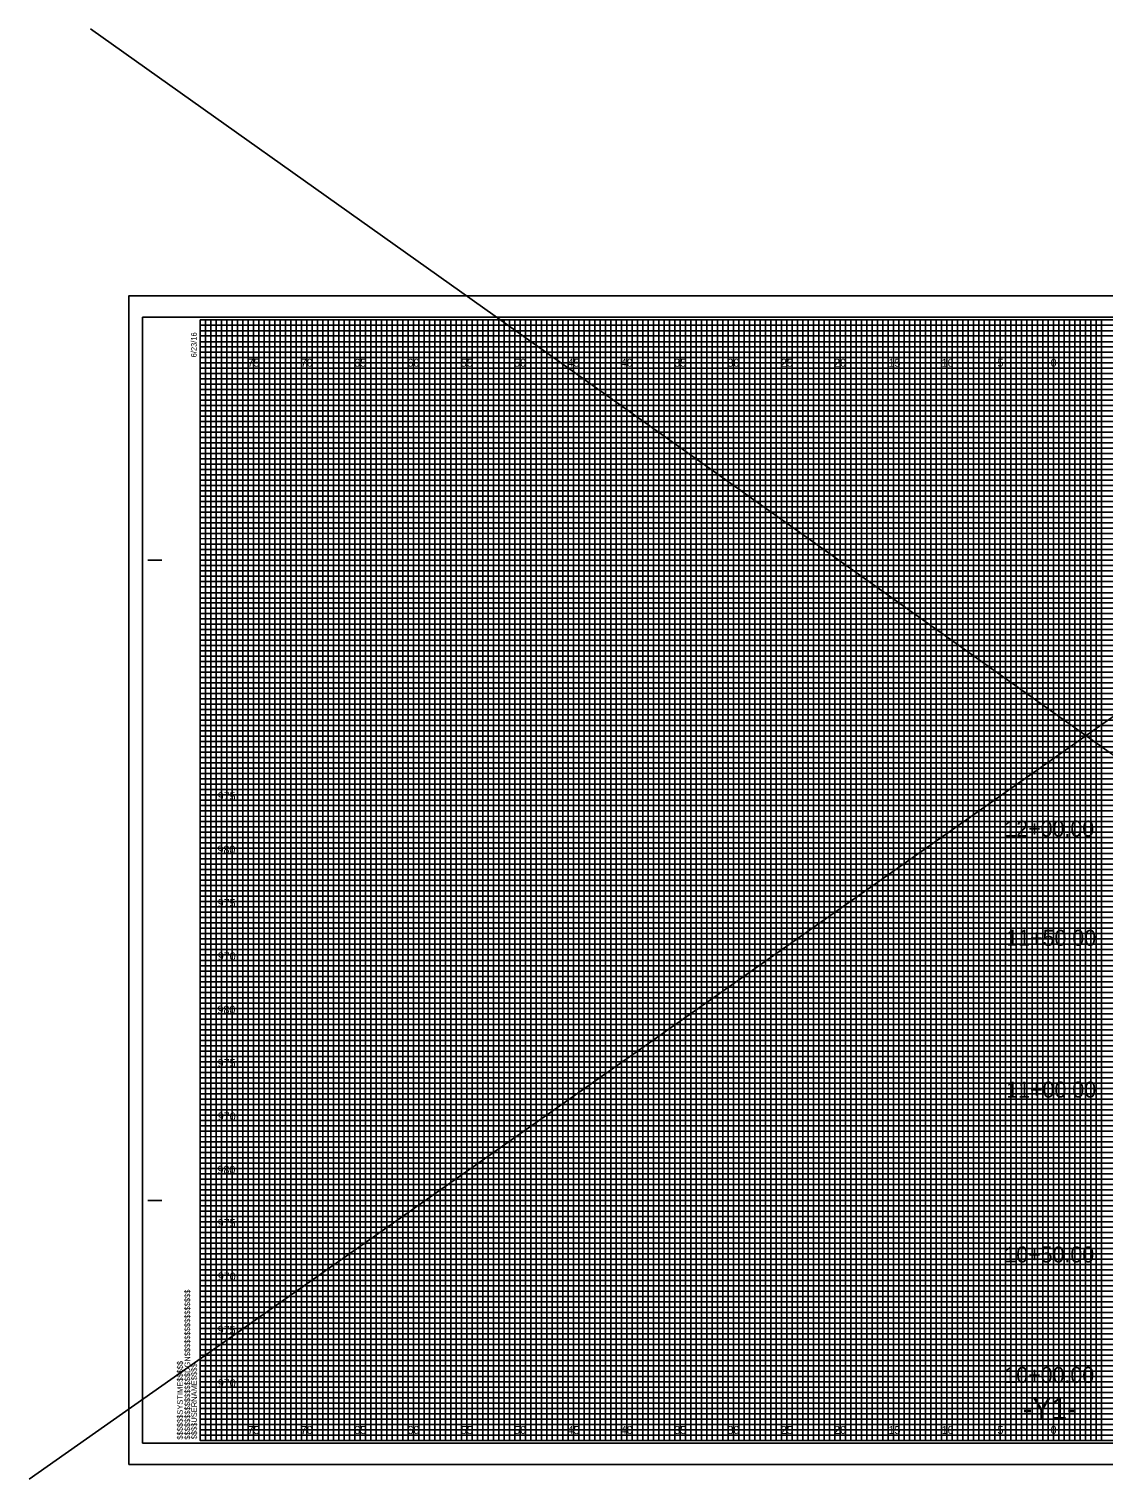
# Model space of a CAD drawing. Extents: x -16 to 178, y -4 to 132.
# Drawn here: x -16.1 to 84.6, y -3.6 to 132.3 of the extents above; entities that cross this region are included whole.
import ezdxf

# ---------------------------------------------------------------- set-up
doc = ezdxf.new("R2010")
doc.units = 0
for name, color, linetype in [('Default', 7, 'Continuous'), ('Exist Cross Section Cell', 7, 'Continuous'), ('Exist XS Center Line Elevation Label', 7, 'Continuous'), ('Exist XS Ground Line', 7, 'Continuous'), ('Prop XS Ditch Standard Text', 7, 'Continuous'), ('Prop XS Dump Level', 7, 'Continuous'), ('Prop XS Finish Grade', 7, 'Continuous'), ('Prop XS Finish Grade Earthwork', 7, 'Continuous'), ('Prop XS Pvmt Edge Slope', 7, 'Continuous'), ('Prop XS SE Text', 7, 'Continuous'), ('Prop XS Side Slope Text', 7, 'Continuous'), ('Prop XS SS Elevation Text', 7, 'Continuous'), ('Prop XS Subgrade CurbGutter', 7, 'Continuous'), ('Prop XS Subgrade Earthwork', 7, 'Continuous')]:
    doc.layers.add(name, color=color, linetype=linetype)

msp = doc.modelspace()

# ---------------------------------------------------------------- linework, layer by layer
at = {"layer": 'Default'}
for p, q in [((178, -1.35), (-10.3, 132.27)), ((-16.05, -3.6), (159.75, 120))]:
    msp.add_line(p, q, dxfattribs=at)
at = {"layer": 'Exist XS Center Line Elevation Label'}
for points in [[(0, 105), (2.5, 105), (2.5, 0), (7.5, 0), (7.5, 105), (12.5, 105), (12.5, 0), (17.5, 0), (17.5, 105), (22.5, 105), (22.5, 0), (27.5, 0), (27.5, 105), (32.5, 105), (32.5, 0), (37.5, 0), (37.5, 105), (42.5, 105), (42.5, 0), (47.5, 0), (47.5, 105), (52.5, 105), (52.5, 0), (57.5, 0), (57.5, 105), (62.5, 105), (62.5, 0), (67.5, 0), (67.5, 105), (72.5, 105), (72.5, 0), (77.5, 0), (77.5, 105), (82.5, 105), (82.5, 0), (87.5, 0)], [(0, 102.5), (137.5, 102.5)], [(0, 92.5), (160, 92.5), (160, 97.5), (0, 97.5)], [(0, 82.5), (160, 82.5), (160, 87.5), (0, 87.5)], [(0, 72.5), (160, 72.5), (160, 77.5), (0, 77.5)], [(0, 62.5), (160, 62.5), (160, 67.5), (0, 67.5)], [(0, 52.5), (160, 52.5), (160, 57.5), (0, 57.5)], [(0, 42.5), (160, 42.5), (160, 47.5), (0, 47.5)], [(0, 32.5), (160, 32.5), (160, 37.5), (0, 37.5)], [(0, 22.5), (160, 22.5), (160, 27.5), (0, 27.5)], [(0, 12.5), (160, 12.5), (160, 17.5), (0, 17.5)], [(0, 2.5), (160, 2.5), (160, 7.5), (0, 7.5)]]:
    msp.add_lwpolyline(points, dxfattribs=at)
at = {"layer": 'Exist XS Ground Line'}
for p, q in [((5, 105), (0, 105)), ((5, 0), (5, 105)), ((15, 105), (10, 105)), ((10, 105), (10, 0)), ((15, 0), (15, 105)), ((25, 105), (20, 105)), ((20, 105), (20, 0)), ((25, 0), (25, 105)), ((35, 105), (30, 105)), ((30, 105), (30, 0)), ((35, 0), (35, 105)), ((45, 105), (40, 105)), ((40, 105), (40, 0)), ((45, 0), (45, 105)), ((55, 105), (50, 105)), ((50, 105), (50, 0)), ((55, 0), (55, 105)), ((65, 105), (60, 105)), ((60, 105), (60, 0)), ((65, 0), (65, 105)), ((75, 105), (70, 105)), ((70, 105), (70, 0)), ((75, 0), (75, 105)), ((85, 105), (80, 105)), ((80, 105), (80, 0)), ((10, 0), (5, 0)), ((20, 0), (15, 0)), ((30, 0), (25, 0)), ((40, 0), (35, 0)), ((50, 0), (45, 0)), ((60, 0), (55, 0)), ((70, 0), (65, 0)), ((80, 0), (75, 0))]:
    msp.add_line(p, q, dxfattribs=at)
for points in [[(0, 100), (160, 100), (160, 95), (0, 95)], [(0, 90), (160, 90), (160, 85), (0, 85)], [(0, 80), (160, 80), (160, 75), (0, 75)], [(0, 70), (160, 70), (160, 65), (0, 65)], [(0, 60), (160, 60), (160, 55), (0, 55)], [(0, 50), (160, 50), (160, 45), (0, 45)], [(0, 40), (160, 40), (160, 35), (0, 35)], [(0, 30), (160, 30), (160, 25), (0, 25)], [(0, 20), (160, 20), (160, 15), (0, 15)], [(0, 10), (160, 10), (160, 5), (0, 5)]]:
    msp.add_lwpolyline(points, dxfattribs=at)
at = {"layer": 'Prop XS Ditch Standard Text'}
for points in [[(0, 0), (0.5, 0), (0.5, 105), (1, 105), (1, 0)], [(1, 0), (1.5, 0), (1.5, 105), (2, 105), (2, 0)], [(2.5, 0), (3, 0), (3, 105), (3.5, 105), (3.5, 0)], [(3.5, 0), (4, 0), (4, 105), (4.5, 105), (4.5, 0)], [(5, 0), (5.5, 0), (5.5, 105), (6, 105), (6, 0)], [(6, 0), (6.5, 0), (6.5, 105), (7, 105), (7, 0)], [(7.5, 0), (8, 0), (8, 105), (8.5, 105), (8.5, 0)], [(8.5, 0), (9, 0), (9, 105), (9.5, 105), (9.5, 0)], [(10, 0), (10.5, 0), (10.5, 105), (11, 105), (11, 0)], [(11, 0), (11.5, 0), (11.5, 105), (12, 105), (12, 0)], [(12.5, 0), (13, 0), (13, 105), (13.5, 105), (13.5, 0)], [(13.5, 0), (14, 0), (14, 105), (14.5, 105), (14.5, 0)], [(15, 0), (15.5, 0), (15.5, 105), (16, 105), (16, 0)], [(16, 0), (16.5, 0), (16.5, 105), (17, 105), (17, 0)], [(17.5, 0), (18, 0), (18, 105), (18.5, 105), (18.5, 0)], [(18.5, 0), (19, 0), (19, 105), (19.5, 105), (19.5, 0)], [(20, 0), (20.5, 0), (20.5, 105), (21, 105), (21, 0)], [(21, 0), (21.5, 0), (21.5, 105), (22, 105), (22, 0)], [(22.5, 0), (23, 0), (23, 105), (23.5, 105), (23.5, 0)], [(23.5, 0), (24, 0), (24, 105), (24.5, 105), (24.5, 0)], [(25, 0), (25.5, 0), (25.5, 105), (26, 105), (26, 0)], [(26, 0), (26.5, 0), (26.5, 105), (27, 105), (27, 0)], [(27.5, 0), (28, 0), (28, 105), (28.5, 105), (28.5, 0)], [(28.5, 0), (29, 0), (29, 105), (29.5, 105), (29.5, 0)], [(30, 0), (30.5, 0), (30.5, 105), (31, 105), (31, 0)], [(31, 0), (31.5, 0), (31.5, 105), (32, 105), (32, 0)], [(32.5, 0), (33, 0), (33, 105), (33.5, 105), (33.5, 0)], [(33.5, 0), (34, 0), (34, 105), (34.5, 105), (34.5, 0)], [(35, 0), (35.5, 0), (35.5, 105), (36, 105), (36, 0)], [(36, 0), (36.5, 0), (36.5, 105), (37, 105), (37, 0)], [(37.5, 0), (38, 0), (38, 105), (38.5, 105), (38.5, 0)], [(38.5, 0), (39, 0), (39, 105), (39.5, 105), (39.5, 0)], [(40, 0), (40.5, 0), (40.5, 105), (41, 105), (41, 0)], [(41, 0), (41.5, 0), (41.5, 105), (42, 105), (42, 0)], [(42.5, 0), (43, 0), (43, 105), (43.5, 105), (43.5, 0)], [(43.5, 0), (44, 0), (44, 105), (44.5, 105), (44.5, 0)], [(45, 0), (45.5, 0), (45.5, 105), (46, 105), (46, 0)], [(46, 0), (46.5, 0), (46.5, 105), (47, 105), (47, 0)], [(47.5, 0), (48, 0), (48, 105), (48.5, 105), (48.5, 0)], [(48.5, 0), (49, 0), (49, 105), (49.5, 105), (49.5, 0)], [(50, 0), (50.5, 0), (50.5, 105), (51, 105), (51, 0)], [(51, 0), (51.5, 0), (51.5, 105), (52, 105), (52, 0)], [(52.5, 0), (53, 0), (53, 105), (53.5, 105), (53.5, 0)], [(53.5, 0), (54, 0), (54, 105), (54.5, 105), (54.5, 0)], [(55, 0), (55.5, 0), (55.5, 105), (56, 105), (56, 0)], [(56, 0), (56.5, 0), (56.5, 105), (57, 105), (57, 0)], [(57.5, 0), (58, 0), (58, 105), (58.5, 105), (58.5, 0)], [(58.5, 0), (59, 0), (59, 105), (59.5, 105), (59.5, 0)], [(60, 0), (60.5, 0), (60.5, 105), (61, 105), (61, 0)], [(61, 0), (61.5, 0), (61.5, 105), (62, 105), (62, 0)], [(62.5, 0), (63, 0), (63, 105), (63.5, 105), (63.5, 0)], [(63.5, 0), (64, 0), (64, 105), (64.5, 105), (64.5, 0)], [(65, 0), (65.5, 0), (65.5, 105), (66, 105), (66, 0)], [(66, 0), (66.5, 0), (66.5, 105), (67, 105), (67, 0)], [(67.5, 0), (68, 0), (68, 105), (68.5, 105), (68.5, 0)], [(68.5, 0), (69, 0), (69, 105), (69.5, 105), (69.5, 0)], [(70, 0), (70.5, 0), (70.5, 105), (71, 105), (71, 0)], [(71, 0), (71.5, 0), (71.5, 105), (72, 105), (72, 0)], [(72.5, 0), (73, 0), (73, 105), (73.5, 105), (73.5, 0)], [(73.5, 0), (74, 0), (74, 105), (74.5, 105), (74.5, 0)], [(75, 0), (75.5, 0), (75.5, 105), (76, 105), (76, 0)], [(76, 0), (76.5, 0), (76.5, 105), (77, 105), (77, 0)], [(77.5, 0), (78, 0), (78, 105), (78.5, 105), (78.5, 0)], [(78.5, 0), (79, 0), (79, 105), (79.5, 105), (79.5, 0)], [(80, 0), (80.5, 0), (80.5, 105), (81, 105), (81, 0)], [(81, 0), (81.5, 0), (81.5, 105), (82, 105), (82, 0)], [(82.5, 0), (83, 0), (83, 105), (83.5, 105), (83.5, 0)], [(83.5, 0), (84, 0), (84, 105), (84.5, 105), (84.5, 0)]]:
    msp.add_lwpolyline(points, dxfattribs=at)
at = {"layer": 'Prop XS Dump Level'}
for p, q in [((0, 104.5), (130, 104.5)), ((130, 103.99), (0, 103.99)), ((0, 103.99), (0, 103.5)), ((0, 103.5), (130, 103.5)), ((130, 102.95), (0, 102.95)), ((0, 102.95), (0, 102)), ((0, 102), (160, 102))]:
    msp.add_line(p, q, dxfattribs=at)
for points in [[(0, 101.5), (135, 101.5), (160, 101.5), (160, 101), (0, 101)], [(0, 100.5), (160, 100.5), (160, 99.5), (0, 99.5)], [(0, 99), (160, 99), (160, 98.5), (0, 98.49)], [(0, 98), (160, 98), (160, 97), (0, 97)], [(0, 96.5), (160, 96.5), (160, 96), (0, 96)], [(0, 95.5), (160, 95.5), (160, 94.5), (0, 94.5)], [(0, 94), (160, 94), (160, 93.5), (0, 93.5)], [(0, 93), (160, 93), (160, 92), (0, 92)], [(0, 91.5), (160, 91.5), (160, 91), (0, 91)], [(0, 90.5), (160, 90.5), (160, 89.5), (0, 89.5)], [(0, 89), (160, 89), (160, 88.5), (0, 88.5)], [(0, 88), (160, 88), (160, 86.98), (160, 86.5), (160, 86), (0, 86)], [(0, 87), (160, 87), (160, 86.5), (0, 86.5)], [(0, 85.5), (160, 85.5), (160, 84.5), (0, 84.52)], [(0, 84.52), (160, 84.5), (160, 84), (0, 84)], [(0, 83.5), (160, 83.5), (160, 83), (0, 83)], [(0, 82), (160, 82), (160, 81.5), (0, 81.5)], [(0, 81), (160, 81), (160, 80.5), (0, 80.5)], [(-0.04, 79.45), (160, 79.45), (160, 78.94), (-0.04, 78.94)], [(0, 78.5), (160, 78.5), (160, 78), (0, 78)], [(0, 77), (160, 77), (160, 76.5), (0, 76.5)], [(0, 76), (160, 76), (160, 75.5), (0, 75.5)], [(0, 74.5), (160, 74.5), (160, 74), (0, 74)], [(0, 73.5), (160, 73.5), (160, 73), (0, 73)], [(0, 72), (160, 72), (160, 71.5), (0, 71.5)], [(0, 71), (160, 71), (160, 70.5), (0, 70.5)], [(0, 69.5), (160, 69.5), (160, 68.99), (0, 69)], [(0, 68.5), (160, 68.5), (160, 68), (0, 68)], [(0, 67), (160, 67), (160, 66.5), (0, 66.5)], [(0, 66), (160, 66), (160, 65.5), (0, 65.5)], [(0, 64.5), (160, 64.5), (160, 64), (0, 64)], [(0, 63.5), (160, 63.5), (160, 63), (0, 63)], [(0, 62), (160, 62), (160, 61.5), (0, 61.5)], [(0, 61), (160, 61), (160, 60.5), (0, 60.5)], [(0, 59.5), (160, 59.5), (160, 59), (0, 59)], [(0, 58.5), (160.03, 58.45), (160, 58), (0, 58)], [(0, 57), (160, 57), (160, 56.5), (0, 56.5)], [(0, 56), (160, 56), (160, 55.5), (0, 55.5)], [(0, 54.5), (160, 54.5), (160, 54), (0, 54)], [(0, 53.5), (160, 53.5), (160, 53), (0, 53)], [(0, 52), (160, 52), (160, 51.5), (0, 51.5)], [(0, 51), (160, 51), (160, 50.5), (0, 50.5)], [(0, 49.5), (160, 49.5), (160, 49), (0, 49)], [(0, 48.5), (160, 48.5), (160, 48), (0, 48)], [(0, 47), (160, 47), (160, 46.5), (0, 46.5)], [(0, 46), (160, 46), (160, 45.5), (0, 45.5)], [(0, 44.5), (160, 44.5), (160, 44), (0, 44)], [(0, 43.5), (160, 43.5), (160, 43), (0, 43)], [(0, 42), (160, 42), (160, 41.5), (0, 41.5)], [(0, 41), (160, 41), (160, 40.5), (0, 40.5)], [(0, 39.5), (160, 39.5), (160, 38.99), (0, 39)], [(0, 38.5), (160, 38.5), (160, 38), (0, 38)], [(0, 37), (160, 37), (160, 36.5), (0, 36.5)], [(0, 36), (160, 36), (160, 35.5), (0, 35.5)], [(0, 34.5), (160, 34.5), (160, 34), (0, 34)], [(0, 33.5), (160, 33.5), (160, 33), (0, 33)], [(0, 32), (160, 32), (160, 31.5), (0, 31.5)], [(0, 31), (160, 31), (160, 30.5), (0, 30.5)], [(0, 29.5), (160, 29.5), (160, 29), (0, 29)], [(0, 28.5), (160.03, 28.46), (160, 28), (0, 28)], [(0, 27), (160, 27), (160, 26.5), (0, 26.5)], [(0, 26), (160, 26), (160, 25.5), (0, 25.5)], [(0, 24.5), (160, 24.5), (160, 24), (0, 24)], [(0, 23.5), (160, 23.5), (160, 23), (0, 23)], [(0, 22), (160, 22), (160, 21.5), (0, 21.5)], [(0, 21), (160, 21), (160, 20.5), (0, 20.5)], [(0, 19.5), (160, 19.5), (160, 19), (0, 19)], [(0, 18.5), (160, 18.5), (160, 18), (0, 18)], [(0, 17), (160, 17), (160, 16.5), (0, 16.5)], [(0, 16), (160, 16), (160, 15.5), (0, 15.5)], [(0, 14.5), (160, 14.5), (160, 14), (0, 14)], [(0, 13.5), (160, 13.5), (160, 13), (0, 13)], [(0, 12), (160, 12), (160, 11.5), (0, 11.5)], [(0, 11), (160, 11), (160, 10.5), (0, 10.5)], [(0, 9.5), (160, 9.5), (160, 9), (0, 9)], [(0, 8.5), (160, 8.5), (160, 8), (0, 8)], [(0, 7), (160, 7), (160, 6.5), (0, 6.5)], [(0, 6), (160, 6), (160, 5.5), (0, 5.5)], [(0, 4.5), (160, 4.5), (160, 4), (0, 4)], [(0, 3.5), (160, 3.5), (160, 3), (0, 3)], [(0, 2), (160, 2), (160, 1.5), (0, 1.5)], [(0, 1), (160, 1), (160, 0.5), (0, 0.5)]]:
    msp.add_lwpolyline(points, dxfattribs=at)
at = {"layer": 'Prop XS Finish Grade Earthwork'}
for p, q in [((5, 0), (5, 105)), ((10, 0), (10, 105)), ((15, 0), (15, 105)), ((20, 0), (20, 105)), ((25, 0), (25, 105)), ((30, 0), (30, 105)), ((35, 0), (35, 105)), ((40, 0), (40, 105)), ((45, 0), (45, 105)), ((50, 0), (50, 105)), ((55, 0), (55, 105)), ((60, 0), (60, 105)), ((65, 0), (65, 105)), ((70, 0), (70, 105)), ((75, 0), (75, 105)), ((80, 0), (80, 105)), ((0, 100), (160, 100)), ((0, 95), (160, 95)), ((0, 90), (160, 90)), ((0, 85), (160, 85)), ((0, 80), (160, 80)), ((0, 75), (160, 75)), ((0, 70), (160, 70)), ((0, 65), (160, 65)), ((0, 60), (160, 60)), ((0, 55), (160, 55)), ((0, 50), (160, 50)), ((0, 45), (160, 45)), ((0, 40), (160, 40)), ((0, 35), (160, 35)), ((0, 30), (160, 30)), ((0, 25), (160, 25)), ((0, 20), (160, 20)), ((0, 15), (160, 15)), ((0, 10), (160, 10)), ((0, 5), (160, 5))]:
    msp.add_line(p, q, dxfattribs=at)
at = {"layer": 'Prop XS SE Text'}
for p, q in [((-4.9, 82.5), (-3.65, 82.5)), ((-4.85, 82.5), (-3.6, 82.5)), ((-4.9, 22.5), (-3.65, 22.5)), ((-4.85, 22.5), (-3.6, 22.5)), ((0, 0), (0, 0)), ((0, 0), (0, 0)), ((0, 0), (0, 0)), ((0, 0), (0, 0)), ((0, 0), (0, 0)), ((0, 0), (0, 0)), ((0, 0), (0, 0))]:
    msp.add_line(p, q, dxfattribs=at)
msp.add_lwpolyline([(160, 105), (0, 105), (0, 0), (160, 0)], close=True, dxfattribs=at)
at = {"layer": 'Prop XS Side Slope Text'}
msp.add_lwpolyline([(-6.7, -2.25), (161.65, -2.25), (161.65, 107.25), (-6.7, 107.25)], close=True, dxfattribs=at)
at = {"layer": 'Prop XS SS Elevation Text'}
msp.add_lwpolyline([(-5.4, -0.25), (161.2, -0.25), (161.2, 105.25), (-5.4, 105.25)], close=True, dxfattribs=at)
at = {"layer": 'Prop XS Subgrade Earthwork'}
for p, q in [((161.65, 107.25), (-6.7, 107.25)), ((-6.7, 107.25), (-6.7, -2.25)), ((-6.7, -2.25), (161.65, -2.25))]:
    msp.add_line(p, q, dxfattribs=at)

# ---------------------------------------------------------------- texts
at = {"layer": 'Exist Cross Section Cell'}
for s, p in [('75', (4.44, 100.62)), ('70', (9.43, 100.62)), ('65', (14.44, 100.62)), ('60', (19.43, 100.62)), ('55', (24.44, 100.62)), ('50', (29.43, 100.62)), ('45', (34.44, 100.62)), ('40', (39.43, 100.62)), ('35', (44.44, 100.62)), ('30', (49.43, 100.62)), ('25', (54.44, 100.62)), ('20', (59.43, 100.62)), ('15', (64.53, 100.62)), ('10', (69.52, 100.62)), ('5', (74.74, 100.62)), ('0', (79.73, 100.62)), ('0', (79.73, 100.62)), ('75', (4.44, 0.62)), ('70', (9.43, 0.62)), ('65', (14.44, 0.62)), ('60', (19.43, 0.62)), ('55', (24.44, 0.62)), ('50', (29.43, 0.62)), ('45', (34.44, 0.62)), ('40', (39.43, 0.62)), ('35', (44.44, 0.62)), ('30', (49.43, 0.62)), ('25', (54.44, 0.62)), ('20', (59.43, 0.62)), ('15', (64.53, 0.62)), ('10', (69.52, 0.62)), ('5', (74.74, 0.62)), ('0', (79.73, 0.62)), ('0', (79.73, 0.62))]:
    msp.add_text(s, height=0.75, dxfattribs=at).set_placement(p)
at = {"layer": 'Prop XS Finish Grade'}
for s, p in [('975', (1.64, 60)), ('980', (1.62, 55)), ('975', (1.64, 50)), ('970', (1.65, 45)), ('980', (1.62, 40)), ('975', (1.64, 35)), ('970', (1.65, 30)), ('980', (1.62, 25)), ('975', (1.64, 20)), ('970', (1.65, 15)), ('975', (1.64, 10)), ('970', (1.65, 5))]:
    msp.add_text(s, height=0.75, dxfattribs=at).set_placement(p)
at = {"layer": 'Prop XS Pvmt Edge Slope'}
for s, p in [('12+00.00', (75.39, 56.59)), ('11+50.00', (75.57, 46.36)), ('11+00.00', (75.57, 32.14)), ('10+50.00', (75.39, 16.69)), ('10+00.00', (75.39, 5.4))]:
    msp.add_text(s, height=1.5, dxfattribs=at).set_placement(p)
at = {"layer": 'Prop XS SE Text'}
for s, p in [('6/23/16', (-0.33, 101.5)), ('$$$$$$$$$$$$$$$$DGN$$$$$$$$$$$$$$$$', (-0.94, 0.09)), ('$$$$$$SYSTIME$$$$$', (-1.63, 0.09)), ('$$$$USERNAME$$$$', (-0.31, 0.12))]:
    msp.add_text(s, height=0.525, rotation=90, dxfattribs=at).set_placement(p)
at = {"layer": 'Prop XS Subgrade CurbGutter'}
msp.add_text('-Y1-', height=2, dxfattribs=at).set_placement((77.11, 2))

doc.saveas('drawing.dxf')
